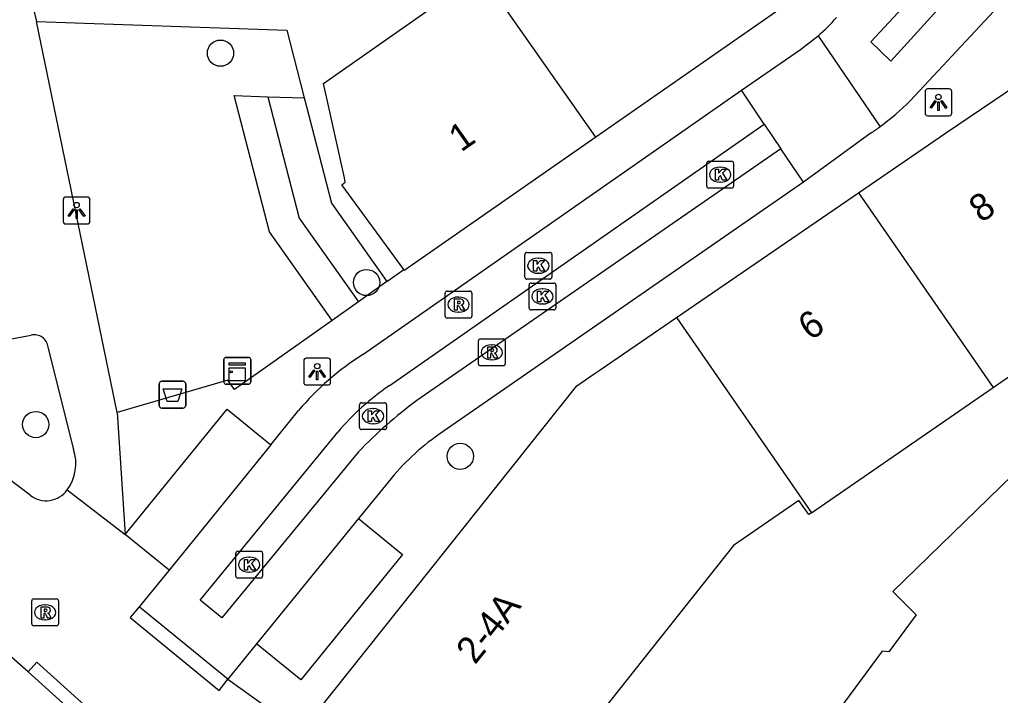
# Model space of a CAD drawing. Extents: x 161771 to 163125, y 382479 to 383177.
# Drawn here: x 161814.5 to 161851, y 383006.74 to 383031.9 of the extents above; entities that cross this region are included whole.
import ezdxf

# ---------------------------------------------------------------- set-up
doc = ezdxf.new("R2010")
doc.units = 0
for name, color, linetype in [('IMGEO_Afvalbak', 7, 'Continuous'), ('IMGEO_Boom', 7, 'Continuous'), ('IMGEO_Groenvoorziening', 7, 'Continuous'), ('IMGEO_Kast', 7, 'Continuous'), ('IMGEO_Kolk', 7, 'Continuous'), ('IMGEO_Lichtpunt', 7, 'Continuous'), ('IMGEO_Pand', 7, 'Continuous'), ('IMGEO_Pand_nummerreeks', 7, 'Continuous'), ('IMGEO_Rijbaan_lokaal_gesloten', 7, 'Continuous'), ('IMGEO_Rijbaan_lokaal_open', 7, 'Continuous'), ('IMGEO_Rioolput', 7, 'Continuous'), ('IMGEO_Voetpad_open', 7, 'Continuous')]:
    doc.layers.add(name, color=color, linetype=linetype)

msp = doc.modelspace()

# ---------------------------------------------------------------- linework, layer by layer
at = {"layer": 'IMGEO_Afvalbak'}
for p, q in [((161819.69, 383017.536), (161819.69, 383018.336)), ((161819.69, 383018.336), (161819.69, 383017.536)), ((161819.79, 383018.436), (161820.58, 383018.436)), ((161820.58, 383018.436), (161819.79, 383018.436)), ((161820.68, 383018.336), (161820.68, 383017.536)), ((161820.68, 383017.536), (161820.68, 383018.336)), ((161820.58, 383017.436), (161819.79, 383017.436)), ((161819.79, 383017.436), (161820.58, 383017.436))]:
    msp.add_line(p, q, dxfattribs=at)
msp.add_lwpolyline([(161819.833, 383018.15), (161820.537, 383018.15), (161820.388, 383017.68), (161819.982, 383017.68), (161819.833, 383018.15)], dxfattribs=at)
for centre, start, end in [((161819.79, 383018.336), 90, 180), ((161819.79, 383018.336), 90, 180), ((161820.58, 383018.336), 0, 90), ((161820.58, 383018.336), 360, 90), ((161819.79, 383017.536), 180, 270), ((161819.79, 383017.536), 180, 270), ((161820.58, 383017.536), 270, 0), ((161820.58, 383017.536), 270, 0)]:
    msp.add_arc(centre, 0.1, start, end, dxfattribs=at)
at = {"layer": 'IMGEO_Boom'}
for centre in [(161821.971, 383030.655), (161827.409, 383022.112), (161815.095, 383016.823), (161830.895, 383015.64)]:
    msp.add_circle(centre, 0.489, dxfattribs=at)
at = {"layer": 'IMGEO_Groenvoorziening'}
for points in [[(161815.123, 383031.829), (161824.437, 383031.507), (161825.086, 383028.985)], [(161826.126, 383020.704), (161823.798, 383023.999), (161822.479, 383029.074), (161823.73, 383029.031)], [(161823.73, 383029.031), (161825.086, 383028.985)], [(161823.73, 383029.031), (161824.904, 383024.513), (161827.104, 383021.398)], [(161825.086, 383028.985), (161825.169, 383028.663), (161826.103, 383025.069), (161828.165, 383022.151)]]:
    msp.add_lwpolyline(points, dxfattribs=at)
at = {"layer": 'IMGEO_Kast'}
for p, q in [((161822.095, 383018.401), (161822.095, 383019.242)), ((161822.095, 383019.242), (161822.095, 383018.401)), ((161822.17, 383019.326), (161823.011, 383019.326)), ((161823.011, 383019.326), (161822.17, 383019.326)), ((161823.095, 383019.251), (161823.095, 383018.41)), ((161823.095, 383018.41), (161823.095, 383019.251)), ((161823.02, 383018.326), (161822.179, 383018.326)), ((161822.179, 383018.326), (161823.02, 383018.326))]:
    msp.add_line(p, q, dxfattribs=at)
for points in [[(161822.29, 383019.116), (161822.89, 383019.116), (161822.89, 383019.031), (161822.29, 383019.031), (161822.29, 383019.116)], [(161822.29, 383018.941), (161822.89, 383018.941), (161822.89, 383018.452), (161822.29, 383018.452), (161822.29, 383018.941)]]:
    msp.add_lwpolyline(points, dxfattribs=at)
msp.add_circle((161822.374, 383018.79), 0.0377, dxfattribs=at)
for centre, start, end in [((161822.173, 383019.248), 92.4484, 184.2845), ((161822.173, 383019.248), 92.4484, 184.2845), ((161823.017, 383019.248), 2.4484, 94.2845), ((161823.017, 383019.248), 2.4484, 94.2845), ((161822.173, 383018.404), 182.4484, 274.2845), ((161822.173, 383018.404), 182.4484, 274.2845), ((161823.017, 383018.404), 272.4484, 4.2845), ((161823.017, 383018.404), 272.4484, 4.2845)]:
    msp.add_arc(centre, 0.0779, start, end, dxfattribs=at)
at = {"layer": 'IMGEO_Kolk'}
for p, q in [((161840.067, 383025.704), (161840.067, 383026.556)), ((161840.142, 383026.63), (161840.994, 383026.63)), ((161840.555, 383026.41), (161840.58, 383026.41)), ((161841.068, 383026.556), (161841.068, 383025.704)), ((161840.994, 383025.63), (161840.142, 383025.63)), ((161840.578, 383025.85), (161840.553, 383025.85)), ((161833.303, 383022.31), (161833.303, 383023.162)), ((161833.378, 383023.236), (161834.23, 383023.236)), ((161834.304, 383023.162), (161834.304, 383022.31)), ((161833.791, 383023.016), (161833.816, 383023.016)), ((161833.814, 383022.456), (161833.789, 383022.456)), ((161834.23, 383022.236), (161833.378, 383022.236)), ((161833.454, 383021.168), (161833.454, 383022.02)), ((161833.529, 383022.094), (161834.381, 383022.094)), ((161834.455, 383022.02), (161834.455, 383021.168)), ((161833.942, 383021.874), (161833.967, 383021.874)), ((161833.965, 383021.314), (161833.94, 383021.314)), ((161834.381, 383021.094), (161833.529, 383021.094)), ((161827.224, 383017.635), (161828.076, 383017.635)), ((161827.149, 383016.709), (161827.149, 383017.561)), ((161827.637, 383017.415), (161827.662, 383017.415)), ((161828.15, 383017.561), (161828.15, 383016.709)), ((161828.076, 383016.635), (161827.224, 383016.635)), ((161827.66, 383016.855), (161827.635, 383016.855)), ((161822.539, 383011.177), (161822.539, 383012.029)), ((161822.614, 383012.103), (161823.466, 383012.103)), ((161823.027, 383011.883), (161823.052, 383011.883)), ((161823.54, 383012.029), (161823.54, 383011.177)), ((161823.466, 383011.103), (161822.614, 383011.103)), ((161823.05, 383011.323), (161823.025, 383011.323))]:
    msp.add_line(p, q, dxfattribs=at)
for points in [[(161840.067, 383025.704), (161840.067, 383026.556)], [(161840.142, 383026.63), (161840.994, 383026.63)], [(161841.068, 383026.556), (161841.068, 383025.704)], [(161840.388, 383026.33), (161840.511, 383026.33), (161840.511, 383026.179), (161840.641, 383026.33), (161840.805, 383026.33), (161840.659, 383026.179), (161840.812, 383025.93), (161840.66, 383025.93), (161840.575, 383026.094), (161840.511, 383026.027), (161840.511, 383025.93), (161840.388, 383025.93), (161840.388, 383026.33)], [(161840.994, 383025.63), (161840.142, 383025.63)], [(161833.303, 383022.31), (161833.303, 383023.162)], [(161833.378, 383023.236), (161834.23, 383023.236)], [(161834.304, 383023.162), (161834.304, 383022.31)], [(161833.624, 383022.936), (161833.747, 383022.936), (161833.747, 383022.785), (161833.877, 383022.936), (161834.041, 383022.936), (161833.895, 383022.785), (161834.048, 383022.536), (161833.896, 383022.536), (161833.811, 383022.7), (161833.747, 383022.633), (161833.747, 383022.536), (161833.624, 383022.536), (161833.624, 383022.936)], [(161834.23, 383022.236), (161833.378, 383022.236)], [(161833.454, 383021.168), (161833.454, 383022.02)], [(161833.529, 383022.094), (161834.381, 383022.094)], [(161834.455, 383022.02), (161834.455, 383021.168)], [(161833.775, 383021.794), (161833.898, 383021.794), (161833.898, 383021.643), (161834.028, 383021.794), (161834.192, 383021.794), (161834.046, 383021.643), (161834.199, 383021.394), (161834.047, 383021.394), (161833.962, 383021.558), (161833.898, 383021.491), (161833.898, 383021.394), (161833.775, 383021.394), (161833.775, 383021.794)], [(161834.381, 383021.094), (161833.529, 383021.094)], [(161827.224, 383017.635), (161828.076, 383017.635)], [(161827.149, 383016.709), (161827.149, 383017.561)], [(161827.47, 383017.335), (161827.593, 383017.335), (161827.593, 383017.184), (161827.723, 383017.335), (161827.887, 383017.335), (161827.741, 383017.184), (161827.894, 383016.935), (161827.742, 383016.935), (161827.657, 383017.099), (161827.593, 383017.032), (161827.593, 383016.935), (161827.47, 383016.935), (161827.47, 383017.335)], [(161828.15, 383017.561), (161828.15, 383016.709)], [(161828.076, 383016.635), (161827.224, 383016.635)], [(161822.539, 383011.177), (161822.539, 383012.029)], [(161822.614, 383012.103), (161823.466, 383012.103)], [(161822.86, 383011.803), (161822.983, 383011.803), (161822.983, 383011.652), (161823.113, 383011.803), (161823.277, 383011.803), (161823.131, 383011.652), (161823.284, 383011.403), (161823.132, 383011.403), (161823.047, 383011.567), (161822.983, 383011.5), (161822.983, 383011.403), (161822.86, 383011.403), (161822.86, 383011.803)], [(161823.54, 383012.029), (161823.54, 383011.177)], [(161823.466, 383011.103), (161822.614, 383011.103)]]:
    msp.add_lwpolyline(points, dxfattribs=at)
for centre, start, end in [((161840.144, 383026.554), 91.552, 178.448), ((161840.144, 383026.554), 91.552, 178.448), ((161840.992, 383026.554), 1.552, 88.448), ((161840.992, 383026.554), 1.552, 88.448), ((161840.144, 383025.706), 181.552, 268.448), ((161840.144, 383025.706), 181.552, 268.448), ((161840.992, 383025.706), 271.552, 358.448), ((161840.992, 383025.706), 271.552, 358.448), ((161833.38, 383023.16), 91.552, 178.448), ((161833.38, 383023.16), 91.552, 178.448), ((161834.228, 383023.16), 1.552, 88.448), ((161834.228, 383023.16), 1.552, 88.448), ((161833.38, 383022.312), 181.552, 268.448), ((161833.38, 383022.312), 181.552, 268.448), ((161833.531, 383022.018), 91.552, 178.448), ((161833.531, 383022.018), 91.552, 178.448), ((161834.228, 383022.312), 271.552, 358.448), ((161834.228, 383022.312), 271.552, 358.448), ((161834.379, 383022.018), 1.552, 88.448), ((161834.379, 383022.018), 1.552, 88.448), ((161833.531, 383021.17), 181.552, 268.448), ((161833.531, 383021.17), 181.552, 268.448), ((161834.379, 383021.17), 271.552, 358.448), ((161834.379, 383021.17), 271.552, 358.448), ((161827.226, 383017.559), 91.552, 178.448), ((161827.226, 383017.559), 91.552, 178.448), ((161828.074, 383017.559), 1.552, 88.448), ((161828.074, 383017.559), 1.552, 88.448), ((161827.226, 383016.711), 181.552, 268.448), ((161827.226, 383016.711), 181.552, 268.448), ((161828.074, 383016.711), 271.552, 358.448), ((161828.074, 383016.711), 271.552, 358.448), ((161822.616, 383012.027), 91.552, 178.448), ((161822.616, 383012.027), 91.552, 178.448), ((161823.464, 383012.027), 1.552, 88.448), ((161823.464, 383012.027), 1.552, 88.448), ((161822.616, 383011.179), 181.552, 268.448), ((161822.616, 383011.179), 181.552, 268.448), ((161823.464, 383011.179), 271.552, 358.448), ((161823.464, 383011.179), 271.552, 358.448)]:
    msp.add_arc(centre, 0.0765, start, end, dxfattribs=at)
for centre, major_axis, ratio, start_param, end_param in [((161840.554, 383026.13), (-0.387, 0.002), 0.722429, 4.712389, 7.853982), ((161840.579, 383026.13), (-0.39, 0.002), 0.717154, 1.570796, 4.712389), ((161833.79, 383022.736), (-0.387, 0.002), 0.722429, 4.712389, 7.853982), ((161833.815, 383022.736), (-0.39, 0.002), 0.717154, 1.570796, 4.712389), ((161833.941, 383021.594), (-0.387, 0.002), 0.722429, 4.712389, 7.853982), ((161833.966, 383021.594), (-0.39, 0.002), 0.717154, 1.570796, 4.712389), ((161827.636, 383017.135), (-0.387, 0.002), 0.722429, 4.712389, 7.853982), ((161827.661, 383017.135), (-0.39, 0.002), 0.717154, 1.570796, 4.712389), ((161823.026, 383011.603), (-0.387, 0.002), 0.722429, 4.712389, 7.853982), ((161823.051, 383011.603), (-0.39, 0.002), 0.717154, 1.570796, 4.712389)]:
    msp.add_ellipse(centre, major_axis=major_axis, ratio=ratio, start_param=start_param, end_param=end_param, dxfattribs=at)
at = {"layer": 'IMGEO_Lichtpunt'}
for p, q in [((161849.094, 383029.321), (161848.286, 383029.321)), ((161849.094, 383029.321), (161848.286, 383029.321)), ((161848.192, 383029.226), (161848.192, 383028.419)), ((161848.192, 383029.226), (161848.192, 383028.419)), ((161849.188, 383028.419), (161849.188, 383029.226)), ((161849.188, 383028.419), (161849.188, 383029.226)), ((161848.286, 383028.325), (161849.094, 383028.325)), ((161848.286, 383028.325), (161849.094, 383028.325)), ((161817.021, 383025.293), (161816.213, 383025.293)), ((161817.021, 383025.293), (161816.213, 383025.293)), ((161816.119, 383025.198), (161816.119, 383024.391)), ((161816.119, 383025.198), (161816.119, 383024.391)), ((161817.115, 383024.391), (161817.115, 383025.198)), ((161817.115, 383024.391), (161817.115, 383025.198)), ((161816.213, 383024.297), (161817.021, 383024.297)), ((161816.213, 383024.297), (161817.021, 383024.297)), ((161825.072, 383019.199), (161825.072, 383018.392)), ((161825.072, 383019.199), (161825.072, 383018.392)), ((161825.974, 383019.294), (161825.166, 383019.294)), ((161825.974, 383019.294), (161825.166, 383019.294)), ((161826.068, 383018.392), (161826.068, 383019.199)), ((161826.068, 383018.392), (161826.068, 383019.199)), ((161825.166, 383018.298), (161825.974, 383018.298)), ((161825.166, 383018.298), (161825.974, 383018.298))]:
    msp.add_line(p, q, dxfattribs=at)
for points in [[(161848.566, 383028.89), (161848.605, 383028.862), (161848.417, 383028.6), (161848.379, 383028.627), (161848.566, 383028.89)], [(161848.668, 383028.842), (161848.715, 383028.842), (161848.715, 383028.52), (161848.668, 383028.52), (161848.668, 383028.842)], [(161848.778, 383028.862), (161848.816, 383028.889), (161849.003, 383028.627), (161848.964, 383028.599), (161848.778, 383028.862)], [(161816.493, 383024.862), (161816.532, 383024.834), (161816.344, 383024.572), (161816.306, 383024.599), (161816.493, 383024.862)], [(161816.595, 383024.814), (161816.642, 383024.814), (161816.642, 383024.492), (161816.595, 383024.492), (161816.595, 383024.814)], [(161816.705, 383024.834), (161816.743, 383024.861), (161816.93, 383024.599), (161816.891, 383024.571), (161816.705, 383024.834)], [(161825.446, 383018.863), (161825.485, 383018.835), (161825.297, 383018.573), (161825.259, 383018.6), (161825.446, 383018.863)], [(161825.548, 383018.815), (161825.595, 383018.815), (161825.595, 383018.493), (161825.548, 383018.493), (161825.548, 383018.815)], [(161825.658, 383018.835), (161825.696, 383018.862), (161825.883, 383018.6), (161825.844, 383018.572), (161825.658, 383018.835)]]:
    msp.add_lwpolyline(points, dxfattribs=at)
for centre in [(161848.691, 383029.024), (161816.618, 383024.996), (161825.571, 383018.997)]:
    msp.add_circle(centre, 0.0994, dxfattribs=at)
for centre, start, end in [((161848.286, 383029.226), 90, 180), ((161848.286, 383029.226), 90, 180), ((161849.094, 383029.226), 0, 90), ((161849.094, 383029.226), 0, 90), ((161848.286, 383028.419), 180, 270), ((161848.286, 383028.419), 180, 270), ((161849.094, 383028.419), 270, 0), ((161849.094, 383028.419), 270, 360), ((161816.213, 383025.198), 90, 180), ((161816.213, 383025.198), 90, 180), ((161817.021, 383025.198), 0, 90), ((161817.021, 383025.198), 0, 90), ((161816.213, 383024.391), 180, 270), ((161816.213, 383024.391), 180, 270), ((161817.021, 383024.391), 270, 0), ((161817.021, 383024.391), 270, 360), ((161825.166, 383019.199), 90, 180), ((161825.166, 383019.199), 90, 180), ((161825.974, 383019.199), 0, 90), ((161825.974, 383019.199), 0, 90), ((161825.166, 383018.392), 180, 270), ((161825.166, 383018.392), 180, 270), ((161825.974, 383018.392), 270, 0), ((161825.974, 383018.392), 270, 360)]:
    msp.add_arc(centre, 0.0946, start, end, dxfattribs=at)
at = {"layer": 'IMGEO_Pand'}
for points in [[(161841.429, 383034.604), (161841.266, 383034.493), (161842.312, 383032.961), (161842.742, 383032.329), (161842.782, 383032.29), (161835.941, 383027.526)], [(161828.794, 383022.597), (161826.486, 383025.752), (161826.616, 383025.85), (161826.581, 383026.006), (161825.991, 383028.69), (161825.806, 383029.529), (161826.013, 383029.674), (161830.107, 383032.546), (161831.656, 383033.633)], [(161835.941, 383027.526), (161831.656, 383033.633)], [(161845.717, 383025.456), (161848.95, 383027.672), (161851.639, 383029.486), (161851.702, 383029.528), (161851.818, 383029.361)], [(161835.941, 383027.526), (161828.92, 383022.637), (161828.817, 383022.565), (161828.794, 383022.597)], [(161838.948, 383020.815), (161845.717, 383025.456)], [(161845.717, 383025.456), (161850.725, 383018.205)], [(161824.98, 383005.379), (161835.231, 383018.26), (161835.873, 383018.707), (161836.104, 383018.865), (161838.948, 383020.815)], [(161838.948, 383020.815), (161843.971, 383013.541)], [(161850.725, 383018.205), (161853.785, 383020.318), (161856.318, 383016.651)], [(161843.971, 383013.541), (161850.725, 383018.205)], [(161856.318, 383016.651), (161854.084, 383014.004), (161852.334, 383015.802), (161846.999, 383010.61), (161847.856, 383009.731), (161846.846, 383008.361), (161846.6, 383008.389), (161842.149, 383002.352), (161841.261, 383003.516), (161839.941, 383002.509), (161839.747, 383002.763), (161839.342, 383002.454), (161837.414, 383000.982), (161836.127, 383000), (161833.959, 382998.347)], [(161843.971, 383013.541), (161843.866, 383013.468), (161843.501, 383013.997), (161841.064, 383012.315), (161836.488, 383006.547), (161834.529, 383004.079), (161831.991, 383000.88)]]:
    msp.add_lwpolyline(points, dxfattribs=at)
at = {"layer": 'IMGEO_Rijbaan_lokaal_gesloten'}
for points in [[(161814.81, 383007.607), (161810.474, 383011.429), (161807.617, 383013.82)], [(161821.134, 383001.897), (161814.81, 383007.607)]]:
    msp.add_lwpolyline(points, dxfattribs=at)
at = {"layer": 'IMGEO_Rijbaan_lokaal_open'}
for points in [[(161851.227, 383036.511), (161846.177, 383031.079), (161846.918, 383030.353), (161851.606, 383035.536)], [(161853.146, 383034.766), (161852.825, 383034.452), (161847.643, 383028.881)], [(161841.365, 383029.274), (161843.557, 383030.796), (161844.216, 383031.301)], [(161844.216, 383031.301), (161846.519, 383027.917)], [(161827.27, 383019.428), (161841.365, 383029.274)], [(161842.207, 383028.009), (161841.365, 383029.274)], [(161828.248, 383018.268), (161842.207, 383028.009)], [(161842.207, 383028.009), (161842.83, 383027.096)], [(161846.187, 383027.684), (161843.67, 383025.845)], [(161842.83, 383027.096), (161829.273, 383017.717)], [(161843.67, 383025.845), (161842.83, 383027.096)], [(161843.67, 383025.845), (161830.093, 383016.447)], [(161823.841, 383016.072), (161824.878, 383017.351)], [(161827.104, 383015.803), (161822.016, 383009.623), (161821.212, 383010.279), (161826.333, 383016.539)], [(161823.841, 383016.072), (161820.056, 383011.399)], [(161828.223, 383014.691), (161827.107, 383013.32)], [(161827.107, 383013.32), (161823.308, 383008.651)], [(161820.056, 383011.399), (161818.95, 383010.034)], [(161822.241, 383007.339), (161818.95, 383010.034)], [(161823.308, 383008.651), (161822.241, 383007.339)]]:
    msp.add_lwpolyline(points, dxfattribs=at)
for centre, radius, start, end in [((161839.86, 383036.329), 6.652, 310.9063, 319.1782), ((161840.639, 383035.911), 9.923, 306.3393, 314.8969), ((161839.799, 383037.139), 11.411, 304.0431, 306.0798), ((161832.945, 383010.477), 10.599, 122.3733, 139.563), ((161833.662, 383010.347), 9.594, 124.3507, 139.8053), ((161840.125, 383003.234), 18.098, 126.8423, 136.0103), ((161835.074, 383009.269), 8.737, 124.7571, 141.6414)]:
    msp.add_arc(centre, radius, start, end, dxfattribs=at)
at = {"layer": 'IMGEO_Rioolput'}
for p, q in [((161830.33, 383020.865), (161830.33, 383021.717)), ((161830.405, 383021.791), (161831.257, 383021.791)), ((161831.331, 383021.717), (161831.331, 383020.865)), ((161830.818, 383021.571), (161830.843, 383021.571)), ((161830.841, 383021.011), (161830.816, 383021.011)), ((161831.257, 383020.791), (161830.405, 383020.791)), ((161831.569, 383019.084), (161831.569, 383019.936)), ((161831.644, 383020.01), (161832.496, 383020.01)), ((161832.057, 383019.79), (161832.082, 383019.79)), ((161832.57, 383019.936), (161832.57, 383019.084)), ((161832.08, 383019.23), (161832.055, 383019.23)), ((161832.496, 383019.01), (161831.644, 383019.01)), ((161815.02, 383010.327), (161815.872, 383010.327)), ((161814.945, 383009.401), (161814.945, 383010.253)), ((161815.433, 383010.107), (161815.458, 383010.107)), ((161815.946, 383010.253), (161815.946, 383009.401)), ((161815.872, 383009.327), (161815.02, 383009.327)), ((161815.456, 383009.547), (161815.431, 383009.547))]:
    msp.add_line(p, q, dxfattribs=at)
for points in [[(161830.33, 383020.865), (161830.33, 383021.717)], [(161830.405, 383021.791), (161831.257, 383021.791)], [(161831.331, 383021.717), (161831.331, 383020.865)], [(161830.919, 383021.489), (161830.667, 383021.491), (161830.667, 383021.091)], [(161830.667, 383021.091), (161830.791, 383021.091), (161830.791, 383021.253), (161830.802, 383021.253)], [(161830.845, 383021.41), (161830.791, 383021.41), (161830.791, 383021.329)], [(161830.791, 383021.329), (161830.843, 383021.329)], [(161830.849, 383021.224), (161830.92, 383021.091), (161831.06, 383021.091), (161830.995, 383021.217)], [(161831.257, 383020.791), (161830.405, 383020.791)], [(161831.569, 383019.084), (161831.569, 383019.936)], [(161831.644, 383020.01), (161832.496, 383020.01)], [(161832.57, 383019.936), (161832.57, 383019.084)], [(161832.158, 383019.708), (161831.906, 383019.71), (161831.906, 383019.31)], [(161831.906, 383019.31), (161832.03, 383019.31), (161832.03, 383019.472), (161832.041, 383019.472)], [(161832.084, 383019.629), (161832.03, 383019.629), (161832.03, 383019.548)], [(161832.03, 383019.548), (161832.082, 383019.548)], [(161832.088, 383019.443), (161832.159, 383019.31), (161832.299, 383019.31), (161832.234, 383019.436)], [(161832.496, 383019.01), (161831.644, 383019.01)], [(161815.02, 383010.327), (161815.872, 383010.327)], [(161814.945, 383009.401), (161814.945, 383010.253)], [(161815.534, 383010.025), (161815.282, 383010.027), (161815.282, 383009.627)], [(161815.46, 383009.946), (161815.406, 383009.946), (161815.406, 383009.865)], [(161815.946, 383010.253), (161815.946, 383009.401)], [(161815.282, 383009.627), (161815.406, 383009.627), (161815.406, 383009.789), (161815.417, 383009.789)], [(161815.406, 383009.865), (161815.458, 383009.865)], [(161815.464, 383009.76), (161815.535, 383009.627), (161815.675, 383009.627), (161815.61, 383009.753)], [(161815.872, 383009.327), (161815.02, 383009.327)]]:
    msp.add_lwpolyline(points, dxfattribs=at)
for centre, radius, start, end in [((161830.407, 383021.715), 0.0765, 91.552, 178.448), ((161830.407, 383021.715), 0.0765, 91.552, 178.448), ((161831.255, 383021.715), 0.0765, 1.552, 88.448), ((161831.255, 383021.715), 0.0765, 1.552, 88.448), ((161830.801, 383021.2), 0.0533, 26.0293, 88.6989), ((161830.827, 383021.518), 0.19, 274.7715, 282.9687), ((161830.851, 383021.314), 0.0964, 77.0061, 93.1865), ((161830.865, 383021.371), 0.0378, 276.6634, 79.6772), ((161830.918, 383021.379), 0.109, 350.3612, 89.416), ((161830.916, 383021.379), 0.112, 277.5842, 350.9817), ((161830.9, 383021.164), 0.108, 29.5134, 73.7905), ((161830.407, 383020.867), 0.0765, 181.552, 268.448), ((161830.407, 383020.867), 0.0765, 181.552, 268.448), ((161831.255, 383020.867), 0.0765, 271.552, 358.448), ((161831.255, 383020.867), 0.0765, 271.552, 358.448), ((161831.646, 383019.934), 0.0765, 91.552, 178.448), ((161831.646, 383019.934), 0.0765, 91.552, 178.448), ((161832.494, 383019.934), 0.0765, 1.552, 88.448), ((161832.494, 383019.934), 0.0765, 1.552, 88.448), ((161832.04, 383019.419), 0.0533, 26.0293, 88.6989), ((161832.066, 383019.737), 0.19, 274.7715, 282.9687), ((161832.09, 383019.533), 0.0964, 77.0061, 93.1865), ((161832.104, 383019.59), 0.0378, 276.6634, 79.6772), ((161832.157, 383019.598), 0.109, 350.3612, 89.416), ((161832.155, 383019.598), 0.112, 277.5842, 350.9817), ((161832.139, 383019.383), 0.108, 29.5134, 73.7905), ((161831.646, 383019.086), 0.0765, 181.552, 268.448), ((161831.646, 383019.086), 0.0765, 181.552, 268.448), ((161832.494, 383019.086), 0.0765, 271.552, 358.448), ((161832.494, 383019.086), 0.0765, 271.552, 358.448), ((161815.022, 383010.251), 0.0765, 91.552, 178.448), ((161815.022, 383010.251), 0.0765, 91.552, 178.448), ((161815.87, 383010.251), 0.0765, 1.552, 88.448), ((161815.87, 383010.251), 0.0765, 1.552, 88.448), ((161815.466, 383009.85), 0.0964, 77.0061, 93.1865), ((161815.48, 383009.907), 0.0378, 276.6634, 79.6772), ((161815.533, 383009.915), 0.109, 350.3612, 89.416), ((161815.416, 383009.736), 0.0533, 26.0293, 88.6989), ((161815.442, 383010.054), 0.19, 274.7715, 282.9687), ((161815.531, 383009.915), 0.112, 277.5842, 350.9817), ((161815.515, 383009.7), 0.108, 29.5134, 73.7905), ((161815.022, 383009.403), 0.0765, 181.552, 268.448), ((161815.022, 383009.403), 0.0765, 181.552, 268.448), ((161815.87, 383009.403), 0.0765, 271.552, 358.448), ((161815.87, 383009.403), 0.0765, 271.552, 358.448)]:
    msp.add_arc(centre, radius, start, end, dxfattribs=at)
for centre, major_axis, ratio, start_param, end_param in [((161830.817, 383021.291), (-0.387, 0.002), 0.722429, 4.712389, 7.853982), ((161830.842, 383021.291), (-0.39, 0.002), 0.717154, 1.570796, 4.712389), ((161832.056, 383019.51), (-0.387, 0.002), 0.722429, 4.712389, 7.853982), ((161832.081, 383019.51), (-0.39, 0.002), 0.717154, 1.570796, 4.712389), ((161815.432, 383009.827), (-0.387, 0.002), 0.722429, 4.712389, 7.853982), ((161815.457, 383009.827), (-0.39, 0.002), 0.717154, 1.570796, 4.712389)]:
    msp.add_ellipse(centre, major_axis=major_axis, ratio=ratio, start_param=start_param, end_param=end_param, dxfattribs=at)
at = {"layer": 'IMGEO_Voetpad_open'}
for points in [[(161814.864, 383032.919), (161815.123, 383031.829)], [(161818.125, 383017.273), (161815.123, 383031.829)], [(161828.165, 383022.151), (161828.794, 383022.597)], [(161828.165, 383022.151), (161827.104, 383021.398)], [(161827.104, 383021.398), (161826.126, 383020.704)], [(161826.126, 383020.704), (161822.488, 383018.123), (161822.25, 383018.481), (161818.125, 383017.273)], [(161814.059, 383019.985), (161814.923, 383020.15)], [(161814.894, 383014.187), (161807.719, 383019.615)], [(161815.552, 383019.706), (161816.505, 383015.899)], [(161818.125, 383017.273), (161818.421, 383012.725)], [(161818.421, 383012.725), (161822.216, 383017.393), (161823.841, 383016.072)], [(161816.268, 383014.386), (161818.421, 383012.725)], [(161827.107, 383013.32), (161828.745, 383011.987), (161824.96, 383007.314), (161823.308, 383008.651)], [(161820.056, 383011.399), (161818.421, 383012.725)], [(161818.95, 383010.034), (161818.616, 383009.639), (161821.927, 383006.924), (161822.241, 383007.339)], [(161821.134, 383001.897), (161821.477, 383002.244), (161815.142, 383007.971), (161814.81, 383007.607)], [(161822.241, 383007.339), (161824.98, 383005.379)]]:
    msp.add_lwpolyline(points, dxfattribs=at)
for centre, radius, start, end in [((161815.046, 383019.656), 0.509, 5.6204, 103.9444), ((161814.884, 383015.378), 1.703, 324.3701, 17.8246), ((161815.485, 383014.952), 0.966, 232.32, 324.162)]:
    msp.add_arc(centre, radius, start, end, dxfattribs=at)

# ---------------------------------------------------------------- texts
at = {"layer": 'IMGEO_Pand_nummerreeks'}
for s, rotation, p in [('1', 35.0536, (161830.924, 383026.947)), ('8', 34.6296, (161850.281, 383024.313)), ('6', 34.6296, (161843.923, 383019.923)), ('2-4A', 51.5605, (161831.445, 383007.852))]:
    msp.add_text(s, height=1, rotation=rotation, dxfattribs=at).set_placement(p)

doc.saveas('drawing.dxf')
